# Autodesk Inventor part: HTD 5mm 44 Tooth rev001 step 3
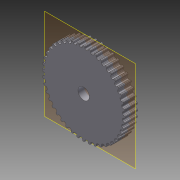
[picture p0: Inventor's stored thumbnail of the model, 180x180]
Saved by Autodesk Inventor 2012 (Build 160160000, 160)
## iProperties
Created: 2011-12
Part Number: HTD 5mm 44 Tooth rev001 step 3
Document SubType Name: Modeling
Designer: Alex
Density: 2.71 g/cm^3
Material: Aluminum-6061
Author: Alex
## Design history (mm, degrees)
sketch "Sketch2"
  geometry: C1 r 34.442 at (0, 0); 1 further point
  constraints: 1 centre point, 1 coincident
  dimensions: "d176" = 68.8848 diameter of C1
extrude "Extrusion1" new body sketch "Sketch2" distance "d177" = 10.5664; taper "d178" = 0 deg
sketch "Sketch1"
  geometry: L1 (0, 0)-(0, 28.7); L2 (-28.232, 0)-(27.326, 0); L3 (1.814, 25.366)-(0, 0); L4 (-1.814, 25.366)-(0, 0); L5 (2.008, 32.35)-(2.616, 32.306); L6 (0.867, 34.03)-(1.026, 33.219); L7 (3.985, 33.807)-(3.712, 33.027); L8 (-34.009, 35.07)-(35.07, 34.009); L9 (35.07, 34.009)-(34.009, -35.07); L10 (34.009, -35.07)-(-35.07, -34.009); L11 (-35.07, -34.009)-(-34.009, 35.07); L12 (-0.867, 34.03)-(-1.026, 33.219); L13 (-2.616, 32.306)-(-2.008, 32.35); L14 (-3.985, 33.807)-(-3.712, 33.027); L15 (-5.701, 33.56)-(-5.743, 32.735); L16 (-7.187, 31.605)-(-6.591, 31.735); L17 (-8.756, 32.896)-(-8.375, 32.162); L18 (-10.419, 32.407)-(-10.343, 31.584); L19 (-11.612, 30.26)-(-11.041, 30.473); L20 (-13.348, 31.315)-(-12.867, 30.643); L21 (-14.925, 30.595)-(-14.733, 29.791); L22 (-15.8, 28.3)-(-15.265, 28.592); L23 (-17.669, 29.097)-(-17.097, 28.5); L24 (-19.127, 28.159)-(-18.822, 27.391); L25 (-19.667, 25.763)-(-19.179, 26.129); L26 (-21.63, 26.286)-(-20.978, 25.777); L27 (-22.94, 25.151)-(-22.529, 24.433); L28 (-23.133, 22.702)-(-22.702, 23.133); L29 (-25.151, 22.94)-(-24.433, 22.529); L30 (-26.286, 21.63)-(-25.777, 20.978); L31 (-26.129, 19.179)-(-25.763, 19.667); L32 (-28.159, 19.127)-(-27.391, 18.822); L33 (-29.097, 17.669)-(-28.5, 17.097); L34 (-28.592, 15.265)-(-28.3, 15.8); L35 (-30.595, 14.925)-(-29.791, 14.733); L36 (-31.315, 13.348)-(-30.643, 12.867); L37 (-30.473, 11.041)-(-30.26, 11.612); L38 (-32.407, 10.419)-(-31.584, 10.343); L39 (-32.896, 8.756)-(-32.162, 8.375); L40 (-31.735, 6.591)-(-31.605, 7.187); L41 (-33.56, 5.701)-(-32.735, 5.743); L42 (-33.807, 3.985)-(-33.027, 3.712); L43 (-32.35, 2.008)-(-32.306, 2.616); L44 (-34.03, 0.867)-(-33.219, 1.026); L45 (-34.03, -0.867)-(-33.219, -1.026); L46 (-32.306, -2.616)-(-32.35, -2.008); L47 (-33.807, -3.985)-(-33.027, -3.712); L48 (-33.56, -5.701)-(-32.735, -5.743); L49 (-31.605, -7.187)-(-31.735, -6.591); L50 (-32.896, -8.756)-(-32.162, -8.375); L51 (-32.407, -10.419)-(-31.584, -10.343); L52 (-30.26, -11.612)-(-30.473, -11.041); L53 (-31.315, -13.348)-(-30.643, -12.867); L54 (-30.595, -14.925)-(-29.791, -14.733); L55 (-28.3, -15.8)-(-28.592, -15.265); L56 (-29.097, -17.669)-(-28.5, -17.097); L57 (-28.159, -19.127)-(-27.391, -18.822); L58 (-25.763, -19.667)-(-26.129, -19.179); L59 (-26.286, -21.63)-(-25.777, -20.978); L60 (-25.151, -22.94)-(-24.433, -22.529); L61 (-22.702, -23.133)-(-23.133, -22.702); L62 (-22.94, -25.151)-(-22.529, -24.433); L63 (-21.63, -26.286)-(-20.978, -25.777); L64 (-19.179, -26.129)-(-19.667, -25.763)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; A1 r 0.508 centre (0.368, 33.932) between (0.867, 34.03) and (0.374, 34.44); A2 r 1.08 centre (2.085, 33.426) between (1.026, 33.219) and (2.008, 32.35); A3 r 0.508 centre (4.465, 33.639) between (4.531, 34.143) and (3.985, 33.807); A4 r 1.08 centre (2.693, 33.383) between (2.616, 32.306) and (3.712, 33.027); A5 r 34.442 centre (0, 0) between (4.531, 34.143) and (0.374, 34.44); A6 r 34.442 centre (0, 0) between (-0.374, 34.44) and (-4.531, 34.143); A7 r 0.508 centre (-0.368, 33.932) between (-0.374, 34.44) and (-0.867, 34.03); A8 r 1.08 centre (-2.085, 33.426) between (-2.008, 32.35) and (-1.026, 33.219); A9 r 1.08 centre (-2.693, 33.383) between (-3.712, 33.027) and (-2.616, 32.306); A10 r 0.508 centre (-4.465, 33.639) between (-3.985, 33.807) and (-4.531, 34.143); A11 r 34.442 centre (0, 0) between (-5.271, 34.037) and (-9.344, 33.151); A12 r 0.508 centre (-5.194, 33.535) between (-5.271, 34.037) and (-5.701, 33.56); A13 r 1.08 centre (-6.821, 32.789) between (-6.591, 31.735) and (-5.743, 32.735); A14 r 1.08 centre (-7.417, 32.66) between (-8.375, 32.162) and (-7.187, 31.605); A15 r 0.508 centre (-9.206, 32.662) between (-8.756, 32.896) and (-9.344, 33.151); A16 r 34.442 centre (0, 0) between (-10.062, 32.94) and (-13.967, 31.483); A17 r 0.508 centre (-9.913, 32.454) between (-10.062, 32.94) and (-10.419, 32.407); A18 r 1.08 centre (-11.418, 31.485) between (-11.041, 30.473) and (-10.343, 31.584); A19 r 1.08 centre (-11.989, 31.272) between (-12.867, 30.643) and (-11.612, 30.26); A20 r 0.508 centre (-13.761, 31.019) between (-13.348, 31.315) and (-13.967, 31.483); A21 r 34.442 centre (0, 0) between (-14.647, 31.173) and (-18.305, 29.175); A22 r 0.508 centre (-14.431, 30.713) between (-14.647, 31.173) and (-14.925, 30.595); A23 r 1.08 centre (-15.782, 29.539) between (-15.265, 28.592) and (-14.733, 29.791); A24 r 1.08 centre (-16.318, 29.247) between (-17.097, 28.5) and (-15.8, 28.3); A25 r 0.508 centre (-18.035, 28.745) between (-17.669, 29.097) and (-18.305, 29.175); A26 r 34.442 centre (0, 0) between (-18.934, 28.771) and (-22.271, 26.273); A27 r 0.508 centre (-18.655, 28.347) between (-18.934, 28.771) and (-19.127, 28.159); A28 r 1.08 centre (-19.826, 26.993) between (-19.179, 26.129) and (-18.822, 27.391); A29 r 1.08 centre (-20.314, 26.627) between (-20.978, 25.777) and (-19.667, 25.763); A30 r 0.508 centre (-21.943, 25.886) between (-21.63, 26.286) and (-22.271, 26.273); A31 r 34.442 centre (0, 0) between (-22.836, 25.784) and (-25.784, 22.836); A32 r 0.508 centre (-22.499, 25.403) between (-22.836, 25.784) and (-22.94, 25.151); A33 r 1.08 centre (-23.465, 23.896) between (-22.702, 23.133) and (-22.529, 24.433); A34 r 1.08 centre (-23.896, 23.465) between (-24.433, 22.529) and (-23.133, 22.702); A35 r 0.508 centre (-25.403, 22.499) between (-25.151, 22.94) and (-25.784, 22.836); A36 r 34.442 centre (0, 0) between (-26.273, 22.271) and (-28.771, 18.934); A37 r 0.508 centre (-25.886, 21.943) between (-26.273, 22.271) and (-26.286, 21.63); A38 r 1.08 centre (-26.627, 20.314) between (-25.763, 19.667) and (-25.777, 20.978); A39 r 1.08 centre (-26.993, 19.826) between (-27.391, 18.822) and (-26.129, 19.179); A40 r 0.508 centre (-28.347, 18.655) between (-28.159, 19.127) and (-28.771, 18.934); A41 r 34.442 centre (0, 0) between (-29.175, 18.305) and (-31.173, 14.647); A42 r 0.508 centre (-28.745, 18.035) between (-29.175, 18.305) and (-29.097, 17.669); A43 r 1.08 centre (-29.247, 16.318) between (-28.3, 15.8) and (-28.5, 17.097); A44 r 1.08 centre (-29.539, 15.782) between (-29.791, 14.733) and (-28.592, 15.265); A45 r 0.508 centre (-30.713, 14.431) between (-30.595, 14.925) and (-31.173, 14.647); A46 r 34.442 centre (0, 0) between (-31.483, 13.967) and (-32.94, 10.062); A47 r 0.508 centre (-31.019, 13.761) between (-31.483, 13.967) and (-31.315, 13.348); A48 r 1.08 centre (-31.272, 11.989) between (-30.26, 11.612) and (-30.643, 12.867); A49 r 1.08 centre (-31.485, 11.418) between (-31.584, 10.343) and (-30.473, 11.041); A50 r 0.508 centre (-32.454, 9.913) between (-32.407, 10.419) and (-32.94, 10.062); A51 r 34.442 centre (0, 0) between (-33.151, 9.344) and (-34.037, 5.271); A52 r 0.508 centre (-32.662, 9.206) between (-33.151, 9.344) and (-32.896, 8.756); A53 r 1.08 centre (-32.66, 7.417) between (-31.605, 7.187) and (-32.162, 8.375); A54 r 1.08 centre (-32.789, 6.821) between (-32.735, 5.743) and (-31.735, 6.591); A55 r 0.508 centre (-33.535, 5.194) between (-33.56, 5.701) and (-34.037, 5.271); A56 r 34.442 centre (0, 0) between (-34.143, 4.531) and (-34.44, 0.374); A57 r 0.508 centre (-33.639, 4.465) between (-34.143, 4.531) and (-33.807, 3.985); A58 r 1.08 centre (-33.383, 2.693) between (-32.306, 2.616) and (-33.027, 3.712); A59 r 1.08 centre (-33.426, 2.085) between (-33.219, 1.026) and (-32.35, 2.008); A60 r 0.508 centre (-33.932, 0.368) between (-34.03, 0.867) and (-34.44, 0.374); A61 r 34.442 centre (0, 0) between (-34.44, -0.374) and (-34.143, -4.531); A62 r 0.508 centre (-33.932, -0.368) between (-34.44, -0.374) and (-34.03, -0.867); A63 r 1.08 centre (-33.426, -2.085) between (-32.35, -2.008) and (-33.219, -1.026); A64 r 1.08 centre (-33.383, -2.693) between (-33.027, -3.712) and (-32.306, -2.616)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; 3 further points; 1 other entity
  constraints: 440 point on circle, 272 end point, 220 centre point, 6 symmetric about line, 3 tangent, 2 perpendicular, 1 coincident, 1 point on line, 1 vertical, 929 other
  dimensions: "d4" = 1.016 diameter of A1; "d27" = 62.11785 dimension on L3 L1; "d47" = 2.159 diameter of A2; "d66" = 0.3683 distance from line of A1.centre L1; "d82" = 0.3048 distance from line of L3 A2.centre; "d97" = 34.544 distance from line of point (0, 0) L11; "d98" = 34.544 distance from line of point (0, 0) L8; "d99" = 89.12 deg angle of L11 L2; "d101" = 69.088 distance between parallel lines of L9 L11; "d131" = 360 deg dimension on point (0, 0) A3.start (derived)
extrude "Extrusion2" cut sketch "Sketch1" stored distance "d179" = 0; taper "d180" = 0 deg
sketch "Sketch3"
  geometry: C1 r 4.763 at (0, 0); A1 r 34.442 centre (0, 0) between (25.784, -22.836) and (26.273, -22.271) reference
  constraints: 1 centre point, 1 coincident
  dimensions: "d181" = 9.525 diameter of C1
extrude "Extrusion3" cut sketch "Sketch3" stored distance "d182" = 25.4; taper "d183" = 0 deg
workplane "Work Plane1"
body "Solid1"
node "Image2"
other parameters: "d0" = 68.8848, "d46" = 2.032
